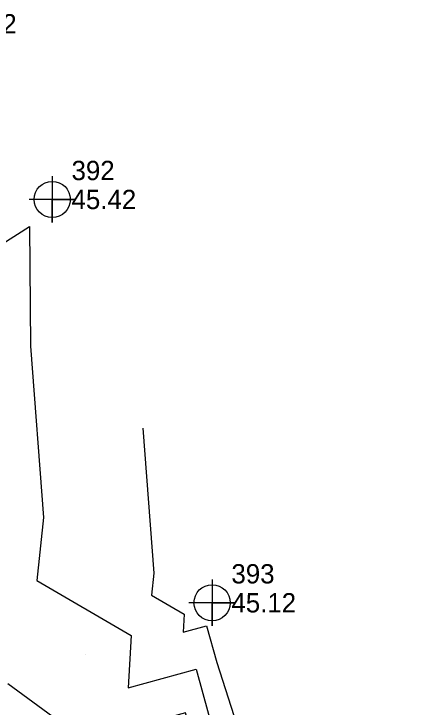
# Model space of a CAD drawing. Extents: x 2090860 to 2091277, y 159470 to 160080.
# Drawn here: x 2091170.8 to 2091224.8, y 159663.1 to 159752.9 of the extents above; entities that cross this region are included whole.
import ezdxf

# ---------------------------------------------------------------- set-up
doc = ezdxf.new("R2010")
doc.units = 0
for name, color, linetype in [('DTM Contours Minor', 7, 'Continuous'), ('Exist DTM QL2 LIDAR Elevation Point', 7, 'Continuous'), ('Exist DTM Regular Point CELL', 7, 'Continuous'), ('Exist DTM Regular Point Cogo Elevation', 7, 'Continuous'), ('Exist DTM Regular Point Cogo Number', 7, 'Continuous')]:
    doc.layers.add(name, color=color, linetype=linetype)

msp = doc.modelspace()

# ---------------------------------------------------------------- linework, layer by layer
at = {"layer": 'DTM Contours Minor'}
for points in [[(2091160, 159717.218), (2091172.816, 159725.36), (2091172.93, 159709.849), (2091174.594, 159687.678), (2091173.73, 159679.526), (2091185.967, 159672.414), (2091185.557, 159665.633), (2091194.348, 159668.04), (2091198.143, 159654.212), (2091207.702, 159624.397), (2091208.298, 159619.068), (2091212.623, 159613.426), (2091211.487, 159604.317), (2091218.172, 159603.765), (2091221.756, 159601.382)], [(2091187.469, 159699.242), (2091188.879, 159680.457), (2091188.581, 159677.64), (2091192.809, 159675.182), (2091192.668, 159672.839), (2091195.705, 159673.671), (2091197.017, 159668.893), (2091212.372, 159621), (2091212.643, 159618.58), (2091214.607, 159616.017), (2091214.091, 159611.881), (2091217.127, 159611.63), (2091218.755, 159610.548)], [(2091224.758, 159592.216), (2091219.216, 159595.899), (2091213.64, 159596.36), (2091210, 159594.685), (2091207.351, 159600), (2091204.789, 159605.211), (2091210, 159605.717), (2091210.638, 159610.834), (2091203.954, 159619.556), (2091203.032, 159627.795), (2091199.269, 159639.531), (2091192.991, 159662.41), (2091180.902, 159659.098), (2091180, 159656.907), (2091179.568, 159659.568), (2091178.384, 159660), (2091170, 159666.162)]]:
    msp.add_lwpolyline(points, dxfattribs=at)
at = {"layer": 'Exist DTM QL2 LIDAR Elevation Point'}
msp.add_line((2091180, 159670), (2091180, 159670), dxfattribs=at)
at = {"layer": 'Exist DTM Regular Point CELL'}
for points in [[(2091175.736, 159731.859), (2091175.736, 159725.859), (2091175.736, 159728.859), (2091178.736, 159728.859), (2091172.736, 159728.859)], [(2091196.422, 159679.644), (2091196.422, 159673.644), (2091196.422, 159676.644), (2091199.422, 159676.644), (2091193.422, 159676.644)]]:
    msp.add_lwpolyline(points, dxfattribs=at)
for centre in [(2091175.736, 159728.859), (2091196.422, 159676.644)]:
    msp.add_circle(centre, 2.344, dxfattribs=at)

# ---------------------------------------------------------------- texts
at = {"layer": 'Exist DTM Regular Point Cogo Elevation'}
for s, p in [('45.32', (2091162.771, 159750.347)), ('45.42', (2091178.236, 159727.609)), ('45.12', (2091198.922, 159675.394))]:
    msp.add_text(s, height=2.5, dxfattribs=at).set_placement(p)
at = {"layer": 'Exist DTM Regular Point Cogo Number'}
for s, p in [('392', (2091178.236, 159731.359)), ('393', (2091198.922, 159679.144))]:
    msp.add_text(s, height=2.5, dxfattribs=at).set_placement(p)

doc.saveas('drawing.dxf')
